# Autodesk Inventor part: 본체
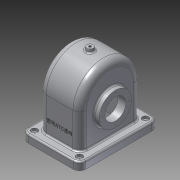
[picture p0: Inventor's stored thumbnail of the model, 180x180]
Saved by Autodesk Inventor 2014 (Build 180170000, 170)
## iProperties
Created: 2016-10
Part Number: 본체
Material: 알루미늄 6061
Document SubType Name: Modeling
Designer: USER
Density: 2.71 g/cm^3
Appearance: 알루미늄 - 평지
Mass: 1165.58 g
Surface Area: 1201.06 cm^2
Volume: 430.103 cm^3
Author: USER
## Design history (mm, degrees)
sketch "스케치2"
  geometry: L1 (-58, -80)-(58, -80); L2 (-58, 0)-(-58, -80); L3 (58, 0)-(58, -80); C1 r 52 at (0, 0); A1 r 58 centre (0, 0) between (58, 0) and (-58, 0); 1 further point
  constraints: 6 end point, 2 centre point, 2 point on circle, 2 tangent, 1 coincident, 1 parallel, 1 perpendicular
  dimensions: "d2" = 104 diameter of C1; "d4" = 6 radial gap between concentric circles of A1 C1; "d6" = 80 distance from line of L1 point (0, 0); "d8" = 138 dimension on A1 L1 (derived); "d9" = 58 distance from line of L2 point (0, 0) (derived); "d10" = 116 distance between parallel lines of L3 L2 (derived)
extrude "돌출1" new body sketch "스케치2" stored distance "d11" = 77; taper "d12" = 0 deg
fillet "모깎기1" dims "d13" = 13
sketch "스케치3"
  geometry: L1 (-58, -80)-(-58, 0) reference; L2 (58, 0)-(58, -80) reference; L3 (58, -80)-(-58, -80) reference; L4 (-52, 0)-(-52, -80); L5 (52, -80)-(52, 0); L6 (-52, -80)-(-52, -91.838); L7 (-52, -91.838)-(52, -91.838); L8 (52, -91.838)-(52, -80); A1 r 58 centre (0, 0) between (58, 0) and (-58, 0) reference; A2 r 52 centre (0, 0) between (52, 0) and (-52, 0); 1 further point
  constraints: 10 end point, 2 parallel, 2 point on circle, 2 point on line, 1 centre point, 1 perpendicular
  dimensions: "d14" = 6 radial gap between concentric circles of A1 A2; "d15" = 6 distance between parallel lines of L1 L4; "d16" = 6 distance between parallel lines of L2 L5
extrude "돌출2" cut sketch "스케치3" stored distance "d17" = 67; taper "d18" = 0 deg
fillet "모깎기2" dims "d19" = 8
sketch "스케치4"
  geometry: L1 (64, -13)-(64, -103) reference; L2 (51, 0)-(0, 0) reference; L3 (-13, -103)-(-13, -13) reference; L4 (0, -116)-(51, -116) reference; L5 (-29.5, -133)-(80.5, -133); L6 (80.5, -133)-(80.5, 17); L7 (80.5, 17)-(-29.5, 17); L8 (-29.5, 17)-(-29.5, -133); L9 (-29.5, -133)-(80.5, 17); L10 (80.5, -133)-(-29.5, 17); A1 r 13 centre (51, -103) between (51, -116) and (64, -103) reference; A2 r 13 centre (51, -13) between (64, -13) and (51, 0) reference; A3 r 13 centre (0, -13) between (0, 0) and (-13, -13) reference; A4 r 13 centre (0, -103) between (-13, -103) and (0, -116) reference; 3 further points
  constraints: 12 end point, 3 midpoint, 2 parallel, 1 coincident, 1 horizontal, 1 perpendicular
  dimensions: "d20" = 150 distance of L5.end L6.end; "d21" = 110 distance of L6.end L7.end
extrude "돌출3" join sketch "스케치4" distance "d22" = 15; taper "d23" = 0 deg
fillet "모깎기3" dims "d24" = 12
sketch "스케치5"
  geometry: A1 r 12 centre (-68.5, 5) between (-68.5, 17) and (-80.5, 5) reference; A2 r 12 centre (-68.5, -121) between (-80.5, -121) and (-68.5, -133) reference; A3 r 12 centre (17.5, -121) between (17.5, -133) and (29.5, -121) reference; A4 r 12 centre (17.5, 5) between (29.5, 5) and (17.5, 17) reference; 1 further point
hole "구멍1" sketch "스케치5" at (17.5, 5), (17.5, -121), (-68.5, -121), (-68.5, 5) diameter "d25" = 5; stored, may be unused: countersink angle "d29" = 90 deg, drill point angle "d31" = 118 deg; dims "d26" = 6, "d27" = 12, "d28" = 5, "d30" = 8
sketch "스케치6"
  geometry: L1 (-25.5, 58)-(25.5, 58) reference; L2 (38.5, 45)-(38.5, -65) reference; L3 (38.5, -65)-(55, -65) reference; L4 (55, -65)-(55, -80) reference; L5 (55, -80)-(33.5, -80) reference; L6 (33.5, -80)-(33.5, 44) reference; L7 (25.5, 52)-(-25.5, 52) reference; L8 (-33.5, 44)-(-33.5, -80) reference; L9 (-33.5, -80)-(-55, -80) reference; L10 (-55, -80)-(-55, -65) reference; L11 (-55, -65)-(-38.5, -65) reference; L12 (-38.5, -65)-(-38.5, 45) reference; L13 (-7.058, 58)-(-6, 64); L14 (-6, 64)-(0, 64); L15 (0, 0)-(0, 86.343); L16 (-7.058, 58)-(0, 58); L17 (-7.058, 58)-(-7.729, 54.192); L18 (-7.729, 54.192)-(0, 54.192); A1 r 13 centre (-25.5, 45) between (-25.5, 58) and (-38.5, 45) reference; A2 r 13 centre (25.5, 45) between (38.5, 45) and (25.5, 58) reference; A3 r 8 centre (25.5, 44) between (33.5, 44) and (25.5, 52) reference; A4 r 8 centre (-25.5, 44) between (-25.5, 52) and (-33.5, 44) reference
  constraints: 12 end point, 4 point on line, 2 perpendicular, 1 collinear, 1 midpoint, 1 parallel
  dimensions: "d32" = 33.5 distance from line of L8 L15.end (derived); "d33" = 100 deg angle of L1 L13; "d35" = 12 diameter of L13.end L15; "d36" = 144 distance between parallel lines of L5 L14
revolve "회전1" sketch "스케치6" stored, may be unused: angle "d37" = 90 deg
sketch "스케치7"
  geometry: L1 (38.5, -15)-(43.5, -15); L2 (-43, -80)-(-55, -80) reference; L3 (-25.5, 58)-(-7.058, 58) reference; L4 (-7.058, 58)-(-6, 64) reference; L5 (-6, 64)-(6, 64) reference; L6 (6, 64)-(7.058, 58) reference; L7 (7.058, 58)-(25.5, 58) reference; L8 (38.5, 45)-(38.5, -65) reference; L9 (38.5, -65)-(55, -65) reference; L10 (55, -65)-(55, -80) reference; L11 (55, -80)-(33.5, -80) reference; L12 (33.5, -80)-(33.5, 44) reference; L13 (25.5, 52)-(-25.5, 52) reference; L14 (-33.5, 44)-(-33.5, -80) reference; L15 (-33.5, -80)-(-55, -80) reference; L16 (-55, -80)-(-55, -65) reference; L17 (-55, -65)-(-38.5, -65) reference; L18 (-38.5, -65)-(-38.5, 45) reference; L19 (43.5, -15)-(43.5, 22.5); L20 (43.5, 22.5)-(38.5, 22.5); L21 (38.5, 22.5)-(38.5, -15); A1 r 13 centre (-25.5, 45) between (-25.5, 58) and (-38.5, 45) reference; A2 r 13 centre (25.5, 45) between (38.5, 45) and (25.5, 58) reference; A3 r 8 centre (25.5, 44) between (33.5, 44) and (25.5, 52) reference; A4 r 8 centre (-25.5, 44) between (-25.5, 52) and (-33.5, 44) reference; 3 further points
  constraints: 8 end point, 4 point on line, 1 collinear, 1 horizontal, 1 parallel, 1 perpendicular
  dimensions: "d38" = 65 distance between parallel lines of L2 L1; "d52" = 5 distance from line of L8 L1.end; "d53" = 75 diameter of L20 L1
revolve "회전3" sketch "스케치7" stored, may be unused: angle "d56" = 90 deg
sketch "스케치8"
  geometry: L1 (-25.5, 58)-(-7.058, 58) reference; L2 (-7.058, 58)-(-6, 64) reference; L3 (-6, 64)-(6, 64) reference; L4 (6, 64)-(7.058, 58) reference; L5 (7.058, 58)-(25.5, 58) reference; L6 (38.5, 45)-(38.5, 22.5) reference; L7 (38.5, 22.5)-(43.5, 22.5) reference; L8 (43.5, 22.5)-(43.5, -52.5) reference; L9 (43.5, -52.5)-(38.5, -52.5) reference; L10 (38.5, -52.5)-(38.5, -65) reference; L11 (38.5, -65)-(55, -65) reference; L12 (55, -65)-(55, -80) reference; L13 (55, -80)-(33.5, -80) reference; L14 (33.5, -80)-(33.5, 44) reference; L15 (25.5, 52)-(-25.5, 52) reference; L16 (-33.5, 44)-(-33.5, -80) reference; L17 (-33.5, -80)-(-55, -80) reference; L18 (-55, -80)-(-55, -65) reference; L19 (-55, -65)-(-38.5, -65) reference; L20 (-38.5, -65)-(-38.5, 45) reference; L21 (18.066, -15)-(-48.5, -15); L22 (-38.5, 16)-(-48.5, 16); L23 (-48.5, 16)-(-48.5, -15); L24 (-38.5, 16)-(-38.5, -15); A1 r 13 centre (-25.5, 45) between (-25.5, 58) and (-38.5, 45) reference; A2 r 13 centre (25.5, 45) between (38.5, 45) and (25.5, 58) reference; A3 r 8 centre (25.5, 44) between (33.5, 44) and (25.5, 52) reference; A4 r 8 centre (-25.5, 44) between (-25.5, 52) and (-33.5, 44) reference; 1 further point
  constraints: 8 end point, 3 point on line, 2 perpendicular, 1 parallel
  dimensions: "d57" = 65 distance between parallel lines of L17 L21; "d58" = 62 diameter of L22 L21; "d59" = 87 distance between parallel lines of L6 L23
revolve "회전4" sketch "스케치8" stored, may be unused: angle "d60" = 90 deg
sketch "스케치9"
  geometry: C1 r 31 at (0, 0) reference; 1 further point
hole "구멍2" sketch "스케치9" at (0, 0) diameter "d61" = 40; stored, may be unused: countersink angle "d65" = 90 deg, drill point angle "d67" = 118 deg; dims "d62" = 6, "d63" = 12, "d64" = 5, "d66" = 8
sketch "스케치10" dims "d68" = 52
  geometry: L1 (0, 0)-(26, 0); C1 r 20 at (0, 0) reference; C2 r 31 at (0, 0) reference; 2 further points
  constraints: 2 coincident, 2 end point, 1 horizontal, 1 horizontal alignment, 2 other
hole "구멍3" sketch "스케치10" at (26, 0), (0, 0), (-15, 0) diameter "d69" = 2.459; stored, may be unused: countersink angle "d73" = 90 deg, drill point angle "d75" = 118 deg; dims "d70" = 6, "d71" = 12, "d72" = 5, "d74" = 8
sketch "스케치11" dims "d79" = 58
  geometry: L1 (0, 0)-(-29, 0); C1 r 20 at (0, 0) reference; 2 further points
  constraints: 2 coincident, 2 end point, 1 horizontal, 1 horizontal alignment, 2 other
hole "구멍4" sketch "스케치11" at (-29, 0) diameter "d80" = 2.459; stored, may be unused: countersink angle "d84" = 90 deg, drill point angle "d86" = 118 deg; dims "d81" = 6, "d82" = 12, "d83" = 5, "d85" = 8
sketch "스케치12"
  geometry: C1 r 6 at (0, 0) reference
hole "구멍5" sketch "스케치12" at (0, 0) diameter "d90" = 4.459; stored, may be unused: countersink angle "d94" = 90 deg, drill point angle "d96" = 118 deg; dims "d91" = 6, "d92" = 12, "d93" = 5, "d95" = 8
fillet "모깎기4" dims "d97" = 3
sketch "스케치13"
  geometry: L1 (-13, 0)-(-13, -62) reference; L2 (68.5, -80)-(-17.5, -80) reference; 2 further points
  constraints: 1 other
  dimensions: "d98" = 38.5 distance from line of L1 point (25.5, -40); "d99" = 40 distance from line of L2 point (25.5, -40)
feature "엠보싱1" sketch "스케치13" dims "d2" = 104, "d4" = 6, "d6" = 80, "d8" = 138 (derived), "d9" = 58 (derived), "d10" = 116 (derived), "d100" = 0.5, "d101" = 0
sketch "스케치14"
  geometry: L1 (-48.5, -35)-(-33.5, -35) reference; L2 (-33.5, -35)-(-33.5, -80) reference; L3 (-33.5, -80)-(-55, -80) reference; L4 (-55, -80)-(-55, -68) reference; L5 (-52, -65)-(-41.5, -65) reference; L6 (-38.5, -62)-(-38.5, -49) reference; L7 (-41.5, -46)-(-48.5, -46) reference; L8 (-48.5, -46)-(-48.5, -42.229) reference; L9 (-48.5, -42.229)-(-40.5, -42.229) reference; L10 (-40.5, -42.229)-(-39.761, -41) reference; L11 (-39.761, -41)-(-40.5, -39.77) reference; L12 (-40.5, -39.77)-(-48.5, -39.77) reference; L13 (-48.5, -39.77)-(-48.5, -35) reference; L14 (33.5, -35)-(43.5, -35) reference; L15 (43.5, -35)-(43.5, -42.77) reference; L16 (43.5, -42.77)-(35.5, -42.77) reference; L17 (35.5, -42.77)-(34.761, -44) reference; L18 (34.761, -44)-(35.5, -45.229) reference; L19 (35.5, -45.229)-(43.5, -45.229) reference; L20 (43.5, -45.229)-(43.5, -52.5) reference; L21 (43.5, -52.5)-(41.5, -52.5) reference; L22 (38.5, -55.5)-(38.5, -62) reference; L23 (41.5, -65)-(52, -65) reference; L24 (55, -68)-(55, -80) reference; L25 (55, -80)-(33.5, -80) reference; L26 (33.5, -80)-(33.5, -35) reference; L27 (25.5, 52)-(2.229, 52) reference; L28 (2.229, 52)-(2.229, 64) reference; L29 (2.229, 64)-(6, 64) reference; L30 (6, 64)-(6.621, 60.479) reference; L31 (9.575, 58)-(25.5, 58) reference; L32 (38.5, 45)-(38.5, 25.5) reference; L33 (41.5, 22.5)-(43.5, 22.5) reference; L34 (43.5, 22.5)-(43.5, 15.23) reference; L35 (43.5, 15.23)-(35.5, 15.23) reference; L36 (35.5, 15.23)-(34.761, 14) reference; L37 (34.761, 14)-(35.5, 12.771) reference; L38 (35.5, 12.771)-(43.5, 12.771) reference; L39 (43.5, 12.771)-(43.5, 5) reference; L40 (43.5, 5)-(33.5, 5) reference; L41 (33.5, 5)-(33.5, 44) reference; L42 (-33.5, 44)-(-33.5, 5) reference; L43 (-33.5, 5)-(-48.5, 5) reference; L44 (-48.5, 5)-(-48.5, 9.771) reference; L45 (-48.5, 9.771)-(-40.5, 9.771) reference; L46 (-40.5, 9.771)-(-39.761, 11) reference; L47 (-39.761, 11)-(-40.5, 12.23) reference; L48 (-40.5, 12.23)-(-48.5, 12.23) reference; L49 (-48.5, 12.23)-(-48.5, 16) reference; L50 (-48.5, 16)-(-41.5, 16) reference; L51 (-38.5, 19)-(-38.5, 45) reference; L52 (-25.5, 58)-(-9.575, 58) reference; L53 (-6.621, 60.479)-(-6, 64) reference; L54 (-6, 64)-(-2.229, 64) reference; L55 (-2.229, 64)-(-2.229, 52) reference; L56 (-2.229, 52)-(-25.5, 52) reference; L57 (33.5, 24.747)-(19.5, 13); L58 (19.5, 13)-(19.5, -15); L59 (-48.5, -35)-(-33.5, -35) reference; L60 (-33.5, -35)-(-33.5, -80) reference; L61 (-33.5, -80)-(-55, -80) reference; L62 (-55, -80)-(-55, -68) reference; L63 (-52, -65)-(-41.5, -65) reference; L64 (-38.5, -62)-(-38.5, -49) reference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; A1 r 3 centre (-52, -68) between (-52, -65) and (-55, -68) reference; A2 r 3 centre (-41.5, -62) between (-41.5, -65) and (-38.5, -62) reference; A3 r 3 centre (-41.5, -49) between (-38.5, -49) and (-41.5, -46) reference; A4 r 3 centre (41.5, -55.5) between (41.5, -52.5) and (38.5, -55.5) reference; A5 r 3 centre (41.5, -62) between (38.5, -62) and (41.5, -65) reference; A6 r 3 centre (52, -68) between (55, -68) and (52, -65) reference; A7 r 8 centre (25.5, 44) between (33.5, 44) and (25.5, 52) reference; A8 r 13 centre (25.5, 45) between (38.5, 45) and (25.5, 58) reference; A9 r 3 centre (41.5, 25.5) between (38.5, 25.5) and (41.5, 22.5) reference; A10 r 8 centre (-25.5, 44) between (-25.5, 52) and (-33.5, 44) reference; A11 r 3 centre (-41.5, 19) between (-41.5, 16) and (-38.5, 19) reference; A12 r 13 centre (-25.5, 45) between (-25.5, 58) and (-38.5, 45) reference; A13 r 3 centre (-52, -68) between (-52, -65) and (-55, -68) reference; A14 r 3 centre (-41.5, -62) between (-41.5, -65) and (-38.5, -62) reference; A15 r 3 centre (-41.5, -49) between (-38.5, -49) and (-41.5, -46) reference; A16 r 3 centre (41.5, -55.5) between (41.5, -52.5) and (38.5, -55.5) reference; A17 r 3 centre (41.5, -62) between (38.5, -62) and (41.5, -65) reference; A18 r 3 centre (52, -68) between (55, -68) and (52, -65) reference; A19 r 8 centre (25.5, 44) between (33.5, 44) and (25.5, 52) reference; A20 r 13 centre (25.5, 45) between (38.5, 45) and (25.5, 58) reference; A21 r 3 centre (41.5, 25.5) between (38.5, 25.5) and (41.5, 22.5) reference; A22 r 8 centre (-25.5, 44) between (-25.5, 52) and (-33.5, 44) reference; A23 r 3 centre (-41.5, 19) between (-41.5, 16) and (-38.5, 19) reference; A24 r 13 centre (-25.5, 45) between (-25.5, 58) and (-38.5, 45) reference; A25 r 3 centre (-52, -68) between (-52, -65) and (-55, -68) reference; A26 r 3 centre (-41.5, -62) between (-41.5, -65) and (-38.5, -62) reference; A27 r 3 centre (-41.5, -49) between (-38.5, -49) and (-41.5, -46) reference; A28 r 3 centre (41.5, -55.5) between (41.5, -52.5) and (38.5, -55.5) reference; A29 r 3 centre (41.5, -62) between (38.5, -62) and (41.5, -65) reference; A30 r 3 centre (52, -68) between (55, -68) and (52, -65) reference; A31 r 8 centre (25.5, 44) between (33.5, 44) and (25.5, 52) reference; A32 r 13 centre (25.5, 45) between (38.5, 45) and (25.5, 58) reference; A33 r 3 centre (41.5, 25.5) between (38.5, 25.5) and (41.5, 22.5) reference; A34 r 8 centre (-25.5, 44) between (-25.5, 52) and (-33.5, 44) reference; A35 r 3 centre (-41.5, 19) between (-41.5, 16) and (-38.5, 19) reference; A36 r 13 centre (-25.5, 45) between (-25.5, 58) and (-38.5, 45) reference; 1 further point
  constraints: 10 end point, 3 perpendicular, 1 midpoint, 1 parallel, 1 point on circle, 1 point on line, 6 other
  dimensions: "d102" = 56 diameter of L57.end L172; "d103" = 50 deg angle of L58 L57; "d104" = 24 distance between parallel lines of L97 L58
revolve "회전5" sketch "스케치14" stored, may be unused: angle "d105" = 90 deg
sketch "스케치15"
  geometry: C1 r 20 at (0, 0) reference; 1 further point
extrude "돌출4" cut sketch "스케치15" stored distance "d106" = 15; taper "d107" = 0 deg
sketch "스케치16"
  geometry: 1 further point
fillet "모깎기5" dims "d108" = 3
node "솔리드1"
pattern_circular "원형 패턴1" dims angle "d77" = 360 deg
pattern_circular "원형 패턴2" dims angle "d88" = 360 deg
node "절단 모서리 투영1"
node "절단 모서리 투영2"
node "절단 모서리 투영3"
node "절단 모서리 투영4"
node "절단 모서리 투영5"
node "절단 모서리 투영6"
node "절단 모서리 투영7"
